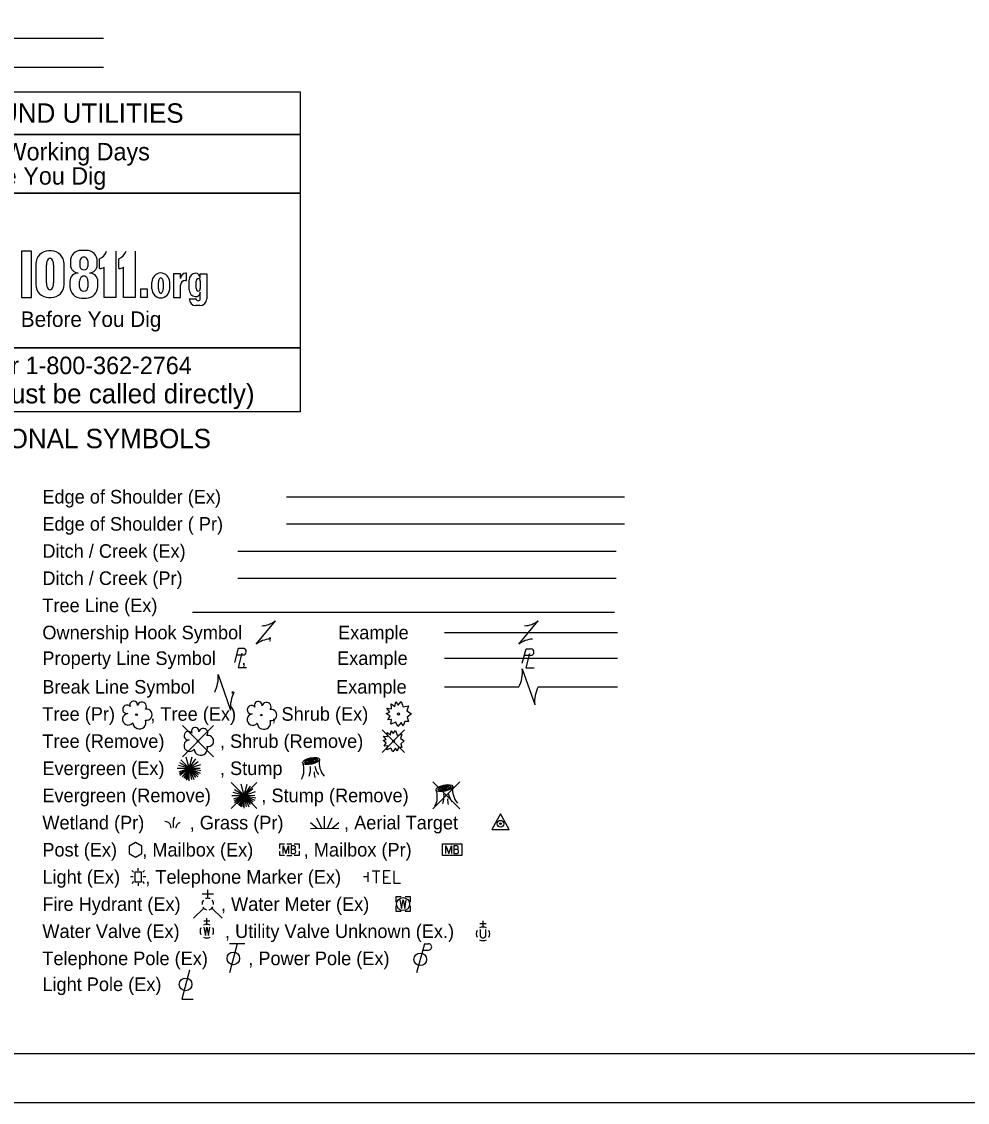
# Model space of a CAD drawing. Extents: x 0 to 34, y 0 to 22.
# Drawn here: x 8.09 to 17.84, y 0 to 11.14 of the extents above; entities that cross this region are included whole.
import ezdxf

# ---------------------------------------------------------------- set-up
doc = ezdxf.new("R2010")
doc.units = 0
for name, color, linetype in [('SH_Border', 7, 'Continuous'), ('SH_Cut_Line', 7, 'Continuous'), ('SH_Data', 7, 'Continuous'), ('SH_Text', 7, 'Continuous')]:
    doc.layers.add(name, color=color, linetype=linetype)

msp = doc.modelspace()

# ---------------------------------------------------------------- linework, layer by layer
at = {"layer": 'SH_Border'}
msp.add_lwpolyline([(1.5, 21.5), (33.5, 21.5), (33.5, 0.5), (1.5, 0.5)], close=True, dxfattribs=at)
at = {"layer": 'SH_Cut_Line'}
msp.add_lwpolyline([(0, 0), (34, 0), (34, 22), (0, 22)], close=True, dxfattribs=at)
at = {"layer": 'SH_Data'}
for p, q in [((8.937, 10.969), (7.687, 10.969)), ((8.937, 10.669), (7.687, 10.669)), ((8.398, 8.779), (8.373, 8.779)), ((8.759, 8.785), (8.71, 8.785)), ((8.896, 8.597), (8.896, 8.699)), ((9.063, 8.777), (9.063, 8.299)), ((9.096, 8.597), (9.096, 8.699)), ((9.263, 8.777), (9.263, 8.299)), ((8.239, 8.645), (8.239, 8.433)), ((8.348, 8.45), (8.348, 8.633)), ((8.423, 8.633), (8.423, 8.45)), ((8.531, 8.433), (8.531, 8.645)), ((8.596, 8.671), (8.596, 8.635)), ((8.695, 8.618), (8.695, 8.676)), ((8.776, 8.676), (8.776, 8.618)), ((8.873, 8.635), (8.873, 8.671)), ((8.944, 8.299), (8.944, 8.611)), ((9.144, 8.299), (9.144, 8.611)), ((9.732, 8.543), (9.659, 8.543)), ((9.659, 8.543), (9.659, 8.299)), ((9.732, 8.495), (9.732, 8.543)), ((9.781, 8.476), (9.792, 8.476)), ((9.792, 8.55), (9.786, 8.55)), ((9.792, 8.476), (9.792, 8.55)), ((9.821, 8.377), (9.821, 8.481)), ((9.935, 8.498), (9.935, 8.544)), ((9.935, 8.544), (10.001, 8.544)), ((10.001, 8.544), (10.001, 8.286)), ((8.591, 8.465), (8.591, 8.414)), ((8.691, 8.405), (8.691, 8.466)), ((8.776, 8.466), (8.776, 8.405)), ((8.879, 8.414), (8.879, 8.465)), ((9.437, 8.39), (9.437, 8.458)), ((9.504, 8.389), (9.504, 8.458)), ((9.552, 8.458), (9.552, 8.389)), ((9.619, 8.458), (9.619, 8.39)), ((9.732, 8.299), (9.732, 8.426)), ((9.893, 8.391), (9.893, 8.468)), ((9.935, 8.468), (9.935, 8.391)), ((8.373, 8.299), (8.398, 8.299)), ((8.711, 8.293), (8.758, 8.293)), ((9.063, 8.299), (8.944, 8.299)), ((9.263, 8.299), (9.144, 8.299)), ((9.659, 8.299), (9.732, 8.299)), ((9.821, 8.286), (9.893, 8.286)), ((9.935, 8.286), (9.935, 8.355)), ((9.931, 8.216), (9.89, 8.216)), ((10.966, 7.121), (5.741, 7.121))]:
    msp.add_line(p, q, dxfattribs=at)
for points in [[(5.741, 10.421), (10.966, 10.421), (10.966, 9.981), (5.741, 9.981)], [(5.741, 9.981), (10.966, 9.981), (10.966, 9.376), (5.741, 9.376)], [(5.741, 9.376), (10.966, 9.376), (10.966, 7.781), (5.741, 7.781)], [(9.321, 8.389), (9.387, 8.389), (9.387, 8.299), (9.321, 8.299)], [(5.741, 7.781), (10.966, 7.781), (10.966, 7.121), (5.741, 7.121)]]:
    msp.add_lwpolyline(points, close=True, dxfattribs=at)
for points in [[(8.093, 8.299), (8.196, 8.299), (8.196, 8.777), (8.093, 8.777), (8.093, 8.299)], [(8.677, 8.551), (8.677, 8.551)], [(8.793, 8.551), (8.793, 8.551)]]:
    msp.add_lwpolyline(points, dxfattribs=at)
for centre, radius, start, end in [((8.373, 8.645), 0.134, 90, 180), ((8.398, 8.645), 0.134, 0, 90), ((8.71, 8.671), 0.114, 90, 180), ((8.759, 8.671), 0.114, 0, 90), ((8.845, 8.821), 0.132, 292.5572, 340.7355), ((9.045, 8.821), 0.132, 292.5572, 340.7355), ((8.68, 8.635), 0.0837, 180, 268.1442), ((8.789, 8.635), 0.0837, 272.2058, 0), ((8.884, 8.728), 0.132, 275.1733, 297.0931), ((9.084, 8.728), 0.132, 275.1733, 297.0931), ((8.677, 8.465), 0.0865, 90, 180), ((8.793, 8.465), 0.0865, 0, 90), ((9.532, 8.458), 0.0956, 92.5886, 180), ((9.524, 8.458), 0.0956, 0, 87.4114), ((9.786, 8.495), 0.0548, 90, 180), ((9.781, 8.426), 0.0493, 90, 180), ((9.889, 8.481), 0.0686, 92.6865, 180), ((9.883, 8.498), 0.0524, 0, 86.9262), ((8.373, 8.433), 0.134, 180, 270), ((8.398, 8.433), 0.134, 270, 0), ((8.711, 8.414), 0.121, 180, 270), ((8.758, 8.414), 0.121, 270, 0), ((9.532, 8.39), 0.0956, 180, 267.4114), ((9.524, 8.39), 0.0956, 272.5886, 0), ((9.89, 8.377), 0.0692, 180, 265.7132), ((9.89, 8.286), 0.0699, 180, 270), ((9.889, 8.355), 0.0467, 264.7825, 0), ((9.931, 8.286), 0.0699, 270, 0)]:
    msp.add_arc(centre, radius, start, end, dxfattribs=at)
for centre, major_axis, ratio, start_param, end_param in [((8.386, 8.633), (0, 0.0723), 0.514403, 4.712389, 7.853982), ((8.735, 8.676), (0.0404, 0), 0.969373, 0, 3.141593), ((8.735, 8.618), (0.0404, 0), 0.818453, 3.141593, 6.283185), ((8.734, 8.466), (0, 0.0535), 0.794529, 4.712389, 7.853982), ((9.528, 8.458), (0, 0.0434), 0.553236, 4.712389, 7.853982), ((9.914, 8.468), (0, 0.0275), 0.777179, 4.712389, 7.853982), ((8.386, 8.45), (0, 0.0723), 0.514403, 1.570796, 4.712389), ((8.734, 8.405), (0.0425, 0), 0.959837, 3.141593, 6.283185), ((9.528, 8.389), (0, 0.046), 0.522014, 1.570796, 4.712389), ((9.914, 8.391), (0, 0.0275), 0.777179, 1.570796, 4.712389), ((9.914, 8.286), (0.0214, 0), 0.959012, 3.141593, 6.283185)]:
    msp.add_ellipse(centre, major_axis=major_axis, ratio=ratio, start_param=start_param, end_param=end_param, dxfattribs=at)
at = {"layer": 'SH_Text'}
for p, q in [((10.824, 6.245), (14.307, 6.245)), ((10.824, 5.965), (14.307, 5.965)), ((10.323, 5.685), (14.223, 5.685)), ((10.323, 5.405), (14.223, 5.405)), ((9.856, 5.055), (14.206, 5.055)), ((10.511, 4.725), (10.711, 4.965)), ((13.219, 4.725), (13.419, 4.965)), ((10.611, 4.845), (10.611, 4.845)), ((12.453, 4.845), (14.236, 4.845)), ((13.319, 4.845), (13.319, 4.845)), ((10.311, 4.614), (10.376, 4.614)), ((10.351, 4.583), (10.351, 4.583)), ((12.453, 4.58), (14.236, 4.58)), ((13.276, 4.61), (13.341, 4.61)), ((13.317, 4.579), (13.317, 4.579)), ((13.254, 4.469), (13.384, 4.101)), ((10.118, 4.413), (10.248, 4.045)), ((12.453, 4.285), (13.219, 4.285)), ((13.319, 4.285), (13.319, 4.285)), ((13.419, 4.285), (14.236, 4.285)), ((10.183, 4.229), (10.183, 4.229)), ((9.751, 3.885), (10.072, 3.564)), ((10.072, 3.885), (9.751, 3.564)), ((11.81, 3.841), (12.042, 3.609)), ((12.042, 3.841), (11.81, 3.609)), ((9.911, 3.725), (9.911, 3.725)), ((11.926, 3.725), (11.926, 3.725)), ((9.822, 3.445), (9.711, 3.474)), ((9.822, 3.445), (9.724, 3.502)), ((9.822, 3.445), (9.735, 3.532)), ((9.822, 3.445), (9.791, 3.56)), ((9.822, 3.445), (9.853, 3.562)), ((9.822, 3.445), (9.888, 3.542)), ((9.822, 3.445), (9.913, 3.515)), ((9.822, 3.445), (9.94, 3.485)), ((9.698, 3.445), (9.822, 3.445)), ((9.822, 3.445), (9.715, 3.406)), ((9.822, 3.445), (9.722, 3.388)), ((9.822, 3.445), (9.724, 3.37)), ((9.822, 3.445), (9.748, 3.358)), ((9.822, 3.445), (9.764, 3.344)), ((9.822, 3.445), (9.78, 3.336)), ((9.822, 3.445), (9.79, 3.323)), ((9.822, 3.445), (9.808, 3.33)), ((9.822, 3.445), (9.935, 3.447)), ((9.822, 3.314), (9.822, 3.445)), ((9.822, 3.445), (9.845, 3.329)), ((9.822, 3.445), (9.87, 3.328)), ((9.822, 3.445), (9.885, 3.35)), ((9.822, 3.445), (9.911, 3.357)), ((9.822, 3.445), (9.917, 3.381)), ((9.822, 3.445), (9.933, 3.396)), ((9.822, 3.445), (9.942, 3.421)), ((11.095, 3.445), (11.095, 3.445)), ((10.252, 3.298), (10.519, 3.031)), ((10.519, 3.298), (10.252, 3.031)), ((10.386, 3.165), (10.299, 3.252)), ((10.386, 3.165), (10.355, 3.28)), ((10.386, 3.165), (10.417, 3.282)), ((10.386, 3.165), (10.452, 3.262)), ((10.386, 3.165), (10.477, 3.235)), ((12.332, 3.304), (12.61, 3.026)), ((12.61, 3.304), (12.332, 3.026)), ((10.262, 3.165), (10.386, 3.165)), ((10.386, 3.165), (10.275, 3.194)), ((10.386, 3.165), (10.279, 3.126)), ((10.386, 3.165), (10.286, 3.108)), ((10.386, 3.165), (10.288, 3.222)), ((10.386, 3.165), (10.288, 3.09)), ((10.386, 3.165), (10.312, 3.078)), ((10.386, 3.165), (10.328, 3.064)), ((10.386, 3.165), (10.344, 3.056)), ((10.386, 3.165), (10.354, 3.043)), ((10.386, 3.165), (10.372, 3.05)), ((10.386, 3.165), (10.504, 3.205)), ((10.386, 3.165), (10.499, 3.167)), ((10.386, 3.034), (10.386, 3.165)), ((10.386, 3.165), (10.409, 3.049)), ((10.386, 3.165), (10.434, 3.048)), ((10.386, 3.165), (10.449, 3.07)), ((10.386, 3.165), (10.476, 3.077)), ((10.386, 3.165), (10.481, 3.101)), ((10.386, 3.165), (10.497, 3.116)), ((10.386, 3.165), (10.507, 3.141)), ((10.386, 3.165), (10.386, 3.165)), ((12.471, 3.165), (12.471, 3.165)), ((12.471, 3.165), (12.471, 3.165)), ((11.187, 2.824), (11.135, 2.93)), ((11.217, 2.825), (11.216, 2.95)), ((11.247, 2.825), (11.296, 2.933)), ((11.139, 2.824), (11.07, 2.881)), ((11.071, 2.823), (11.363, 2.827)), ((11.296, 2.826), (11.363, 2.885)), ((10.829, 2.666), (10.879, 2.666)), ((10.854, 2.605), (10.854, 2.605)), ((12.532, 2.605), (12.532, 2.605)), ((10.829, 2.544), (10.879, 2.544)), ((9.246, 2.373), (9.228, 2.392)), ((9.294, 2.389), (9.294, 2.415)), ((9.361, 2.392), (9.343, 2.373)), ((11.667, 2.275), (11.667, 2.375)), ((9.242, 2.325), (9.216, 2.325)), ((9.246, 2.276), (9.228, 2.258)), ((9.294, 2.325), (9.294, 2.325)), ((9.294, 2.261), (9.294, 2.234)), ((9.361, 2.258), (9.343, 2.276)), ((9.373, 2.325), (9.347, 2.325)), ((11.667, 2.325), (11.617, 2.325)), ((10.073, 2.148), (9.953, 2.148)), ((10.013, 2.105), (10.013, 2.191)), ((10.013, 2.045), (10.013, 2.045)), ((10.013, 2.045), (10.013, 2.045)), ((12.026, 2.045), (12.026, 2.045)), ((9.97, 2.002), (9.866, 1.899)), ((10.003, 1.835), (10.003, 1.898)), ((10.055, 2.002), (10.159, 1.899)), ((10.035, 1.867), (9.972, 1.867)), ((12.881, 1.84), (12.818, 1.84)), ((12.85, 1.808), (12.85, 1.872)), ((10.003, 1.765), (10.003, 1.765)), ((12.822, 1.782), (12.822, 1.713)), ((12.85, 1.738), (12.85, 1.738)), ((12.877, 1.782), (12.877, 1.713)), ((10.396, 1.635), (10.236, 1.635)), ((10.316, 1.635), (10.236, 1.335)), ((12.245, 1.635), (12.165, 1.335)), ((12.228, 1.571), (12.288, 1.571)), ((12.245, 1.635), (12.288, 1.635))]:
    msp.add_line(p, q, dxfattribs=at)
for points in [[(10.29, 4.534), (10.329, 4.683), (10.381, 4.682)], [(10.364, 4.631), (10.325, 4.483), (10.412, 4.483)], [(13.255, 4.53), (13.295, 4.678), (13.346, 4.678)], [(13.33, 4.627), (13.29, 4.479), (13.378, 4.479)], [(11.975, 4.095), (12.005, 4.132), (12.026, 4.079), (12.08, 4.088), (12.063, 4.038), (12.111, 4.008), (12.068, 3.971), (12.08, 3.926), (12.043, 3.929), (12.026, 3.883), (12.005, 3.918), (11.971, 3.877), (11.95, 3.922), (11.899, 3.9), (11.908, 3.947), (11.868, 3.943), (11.891, 3.982), (11.853, 4.011), (11.89, 4.024), (11.859, 4.064), (11.906, 4.059), (11.904, 4.111), (11.942, 4.082), (11.952, 4.131), (11.975, 4.095)], [(11.922, 3.802), (11.948, 3.833), (11.966, 3.788), (12.012, 3.796), (11.998, 3.753), (12.038, 3.728), (12.001, 3.696), (12.012, 3.658), (11.98, 3.66), (11.966, 3.622), (11.948, 3.651), (11.919, 3.616), (11.901, 3.654), (11.858, 3.636), (11.866, 3.676), (11.831, 3.672), (11.851, 3.706), (11.819, 3.73), (11.85, 3.741), (11.824, 3.775), (11.864, 3.771), (11.863, 3.815), (11.895, 3.791), (11.903, 3.832), (11.922, 3.802)], [(9.201, 2.567), (9.266, 2.53), (9.331, 2.567), (9.331, 2.642), (9.266, 2.68), (9.201, 2.642), (9.201, 2.567)], [(10.754, 2.617), (10.754, 2.666), (10.803, 2.666)], [(10.803, 2.544), (10.754, 2.544), (10.754, 2.592)], [(10.789, 2.565), (10.789, 2.645), (10.818, 2.565), (10.846, 2.645), (10.846, 2.565)], [(10.905, 2.608), (10.908, 2.611), (10.91, 2.613), (10.912, 2.615), (10.912, 2.616), (10.913, 2.619), (10.914, 2.621), (10.915, 2.625), (10.915, 2.627), (10.915, 2.63), (10.915, 2.634), (10.913, 2.637), (10.912, 2.639), (10.908, 2.642), (10.906, 2.643), (10.905, 2.644), (10.901, 2.645), (10.871, 2.645), (10.871, 2.565), (10.905, 2.565), (10.91, 2.567), (10.913, 2.571), (10.917, 2.576), (10.918, 2.581), (10.919, 2.587), (10.919, 2.591), (10.918, 2.594), (10.915, 2.6), (10.912, 2.604), (10.905, 2.608), (10.871, 2.608)], [(10.904, 2.666), (10.954, 2.666), (10.954, 2.617)], [(10.954, 2.592), (10.954, 2.544), (10.904, 2.544)], [(12.467, 2.565), (12.467, 2.645), (12.496, 2.565), (12.524, 2.645), (12.524, 2.565)], [(12.583, 2.608), (12.587, 2.611), (12.588, 2.613), (12.59, 2.615), (12.59, 2.616), (12.592, 2.619), (12.592, 2.621), (12.593, 2.625), (12.593, 2.627), (12.593, 2.63), (12.593, 2.634), (12.592, 2.637), (12.59, 2.639), (12.587, 2.642), (12.584, 2.643), (12.583, 2.644), (12.58, 2.645), (12.549, 2.645), (12.549, 2.565), (12.583, 2.565), (12.588, 2.567), (12.592, 2.571), (12.595, 2.576), (12.597, 2.581), (12.597, 2.587), (12.597, 2.591), (12.596, 2.594), (12.593, 2.6), (12.59, 2.604), (12.583, 2.608), (12.549, 2.608)], [(11.708, 2.387), (11.786, 2.387)], [(11.747, 2.387), (11.747, 2.262)], [(11.893, 2.387), (11.825, 2.387), (11.825, 2.262), (11.898, 2.262)], [(11.932, 2.387), (11.932, 2.262), (12, 2.262)], [(11.825, 2.325), (11.873, 2.325)], [(12.006, 2.12), (11.951, 2.12), (11.951, 2.065)], [(12.101, 2.065), (12.101, 2.12), (12.046, 2.12)], [(11.951, 2.025), (11.951, 1.97), (12.006, 1.97)], [(11.993, 2.09), (12.009, 2), (12.026, 2.09), (12.043, 2), (12.059, 2.09)], [(12.046, 1.97), (12.101, 1.97), (12.101, 2.025)], [(9.972, 1.806), (9.988, 1.72), (10.003, 1.806), (10.019, 1.72), (10.035, 1.806)], [(9.824, 1.364), (9.745, 1.064), (9.863, 1.064)]]:
    msp.add_lwpolyline(points, dxfattribs=at)
for points in [[(12.94, 2.815), (13.12, 2.815), (13.03, 2.976)], [(12.432, 2.666), (12.632, 2.666), (12.632, 2.544), (12.432, 2.544)], [(9.261, 2.275), (9.328, 2.275), (9.328, 2.375), (9.261, 2.375)]]:
    msp.add_lwpolyline(points, close=True, dxfattribs=at)
for centre, radius in [((11.979, 4.005), 0.0115), ((9.278, 3.997), 0.0084), ((10.563, 3.993), 0.0072), ((9.911, 3.725), 0.0072), ((11.926, 3.725), 0.00979), ((13.03, 2.873), 0.035), ((13.03, 2.873), 0.008), ((12.026, 2.045), 0.0675), ((10.276, 1.485), 0.065), ((12.203, 1.475), 0.065), ((9.784, 1.216), 0.065)]:
    msp.add_circle(centre, radius, dxfattribs=at)
for centre, radius, start, end in [((10.552, 5.18), 0.267, 273.6945, 306.337), ((13.261, 5.18), 0.267, 273.6945, 306.337), ((10.375, 4.648), 0.0345, 270.471, 81.3281), ((10.669, 4.51), 0.267, 93.6945, 126.337), ((13.377, 4.51), 0.267, 93.6945, 126.337), ((13.341, 4.644), 0.0345, 270.471, 81.3281), ((12.922, 4.437), 0.334, 332.9422, 5.5848), ((9.786, 4.381), 0.334, 332.9422, 5.5848), ((13.716, 4.133), 0.334, 152.9422, 185.5848), ((9.249, 4.098), 0.0395, 354.0047, 205.9741), ((9.333, 4.082), 0.0466, 323.83, 165.0376), ((10.58, 4.078), 0.334, 152.9422, 185.5848), ((10.533, 4.094), 0.0395, 354.0047, 205.9741), ((10.618, 4.078), 0.0466, 323.83, 165.0376), ((9.179, 4.053), 0.0441, 39.0625, 279.5412), ((9.382, 3.998), 0.0574, 259.1453, 101.4596), ((10.464, 4.049), 0.0441, 39.0625, 279.5412), ((10.667, 3.994), 0.0574, 259.1453, 101.4596), ((9.193, 3.95), 0.0592, 96.1722, 320.5737), ((9.307, 3.919), 0.0685, 184.9476, 19.4572), ((10.477, 3.947), 0.0592, 96.1722, 320.5737), ((10.591, 3.915), 0.0685, 184.9476, 19.4572), ((9.812, 3.781), 0.0441, 39.0625, 279.5412), ((9.882, 3.826), 0.0395, 354.0047, 205.9741), ((9.966, 3.81), 0.0466, 323.83, 165.0376), ((9.826, 3.678), 0.0592, 96.1722, 320.5737), ((10.015, 3.726), 0.0574, 259.1453, 101.4596), ((9.94, 3.647), 0.0685, 184.9476, 19.4572), ((10.804, 3.428), 0.2, 331.5338, 20.9269), ((10.82, 3.446), 0.253, 340.7938, 3.5481), ((11.421, 3.548), 0.316, 194.9653, 212.1216), ((11.376, 3.502), 0.215, 171.4106, 219.9194), ((11.291, 3.405), 0.182, 178.7926, 197.1224), ((12.751, 3.222), 0.215, 171.4106, 219.9194), ((12.179, 3.148), 0.2, 331.5338, 20.9269), ((12.195, 3.166), 0.253, 340.7938, 3.5481), ((12.666, 3.125), 0.182, 178.7926, 197.1224), ((12.796, 3.268), 0.316, 194.9653, 212.1216), ((10.013, 2.045), 0.06, 140.021, 184.0629), ((10.013, 2.045), 0.06, 211.8788, 255.8479), ((10.013, 2.045), 0.06, 68.1395, 112.038), ((10.013, 2.045), 0.06, 283.8239, 329.9097), ((10.013, 2.045), 0.06, 356.0165, 39.9889), ((10.003, 1.765), 0.07, 150.0184, 209.9816), ((10.003, 1.765), 0.07, 60.0184, 120.0157), ((10.003, 1.765), 0.07, 330.0184, 29.9816), ((12.85, 1.738), 0.07, 60.0184, 120.0157), ((10.003, 1.765), 0.07, 239.9843, 299.9816), ((12.85, 1.738), 0.07, 150.0184, 209.9816), ((12.85, 1.738), 0.07, 239.9843, 299.9816), ((12.85, 1.725), 0.03, 205.1924, 334.8076), ((12.85, 1.738), 0.07, 330.0184, 29.9816), ((12.289, 1.603), 0.0319, 268.8767, 91.1233)]:
    msp.add_arc(centre, radius, start, end, dxfattribs=at)
for centre, major_axis in [((11.077, 3.52), (0.0868, 0.0187)), ((11.077, 3.52), (0.0651, 0.0141)), ((11.077, 3.52), (0.0488, 0.0105)), ((11.077, 3.52), (0.0275, 0.0059)), ((11.077, 3.52), (0.0154, 0.0033)), ((12.452, 3.24), (0.0868, 0.0187)), ((12.452, 3.24), (0.0651, 0.0141)), ((12.452, 3.24), (0.0488, 0.0105)), ((12.452, 3.24), (0.0275, 0.0059)), ((12.452, 3.24), (0.0154, 0.0033))]:
    msp.add_ellipse(centre, major_axis=major_axis, ratio=0.36865, dxfattribs=at)
for points in [[(9.571, 2.9), (9.612, 2.883), (9.63, 2.829)], [(9.658, 2.833), (9.658, 2.881), (9.664, 2.925), (9.673, 2.946)], [(9.686, 2.826), (9.697, 2.865), (9.727, 2.888)]]:
    msp.add_spline(points, degree=3, dxfattribs=at)

# ---------------------------------------------------------------- texts
at = {"layer": 'SH_Data'}
for s, height, p in [('UNDERGROUND UTILITIES', 0.2, (6.301, 10.101)), ('Contact Two Working Days', 0.18, (6.499, 9.713)), ('Before You Dig', 0.18, (7.334, 9.463)), ('Before You Dig', 0.15972, (8.085, 7.996)), ('OHIO811, 8-1-1, or 1-800-362-2764', 0.18, (6.007, 7.509)), ('(Non-members must be called directly)', 0.2, (5.902, 7.208))]:
    msp.add_text(s, height=height, dxfattribs=at).set_placement(p)
at = {"layer": 'SH_Text'}
for s, height, p in [('CONVENTIONAL SYMBOLS', 0.2, (6.568, 6.745)), ('Edge of Shoulder (Ex)', 0.14, (8.307, 6.175)), ('Edge of Shoulder ( Pr)', 0.14, (8.307, 5.895)), ('Ditch / Creek (Ex)', 0.14, (8.307, 5.615)), ('Ditch / Creek (Pr)', 0.14, (8.307, 5.335)), ('Tree Line (Ex)', 0.14, (8.307, 5.055)), ('Ownership Hook Symbol     ,             Example', 0.14, (8.307, 4.775)), ('Property Line Symbol     ,                  Example', 0.14, (8.307, 4.51)), ('Break Line Symbol       ,                    Example', 0.14, (8.307, 4.215)), ('Tree (Pr)       , Tree (Ex)       , Shrub (Ex)', 0.14, (8.307, 3.935)), ('Tree (Remove)           , Shrub (Remove)', 0.14, (8.307, 3.655)), ('Evergreen (Ex)           , Stump ', 0.14, (8.307, 3.375)), ('Evergreen (Remove)          , Stump (Remove)', 0.14, (8.307, 3.095)), ('Wetland (Pr)         , Grass (Pr)            , Aerial Target    ', 0.14, (8.307, 2.815)), ('Post (Ex)     , Mailbox (Ex)          , Mailbox (Pr)', 0.14, (8.307, 2.535)), ('Light (Ex)     , Telephone Marker (Ex)     ', 0.14, (8.307, 2.255)), ('Fire Hydrant (Ex)        , Water Meter (Ex)', 0.14, (8.307, 1.975)), ('Water Valve (Ex)         , Utility Valve Unknown (Ex.)', 0.14, (8.307, 1.695)), ('Telephone Pole (Ex)        , Power Pole (Ex)', 0.14, (8.307, 1.415)), ('Light Pole (Ex)     ', 0.14, (8.307, 1.148))]:
    msp.add_text(s, height=height, dxfattribs=at).set_placement(p)

doc.saveas('drawing.dxf')
